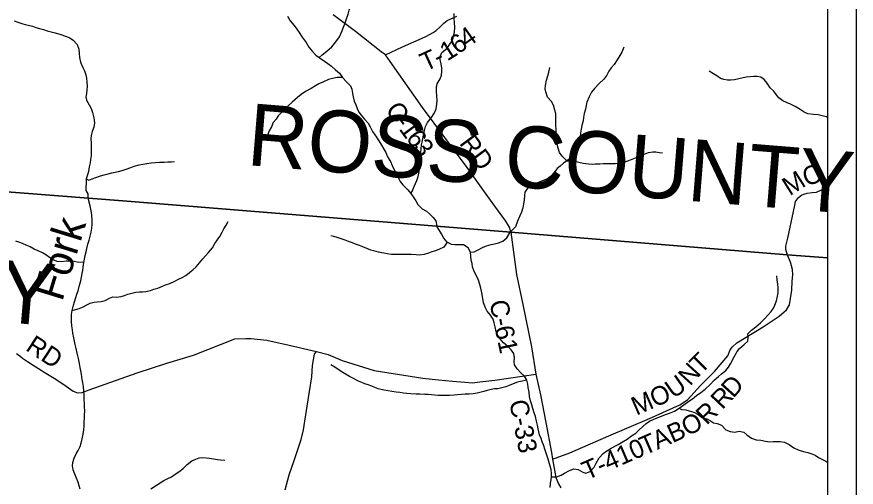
# Model space of a CAD drawing. Extents: x 0 to 34, y 0 to 22.
# Drawn here: x 6.52 to 9.087, y 18.193 to 19.631 of the extents above; entities that cross this region are included whole.
import ezdxf

# ---------------------------------------------------------------- set-up
doc = ezdxf.new("R2010")
doc.units = 0
for name, color, linetype in [('Default', 7, 'Continuous'), ('GM_X_County_Road', 7, 'Continuous'), ('GM_X_County_Road_Text', 7, 'Continuous'), ('GM_X_County_Text', 7, 'Continuous'), ('GM_X_Minor_River', 7, 'Continuous'), ('GM_X_Minor_River_Text', 7, 'Continuous'), ('GM_X_Township_Road', 7, 'Continuous'), ('GM_X_Township_Road_Text', 7, 'Continuous'), ('SH_Cut_Line', 7, 'Continuous')]:
    doc.layers.add(name, color=color, linetype=linetype)

msp = doc.modelspace()

# ---------------------------------------------------------------- linework, layer by layer
at = {"layer": 'Default'}
for points in [[(9.087, 13.8822), (2.1062, 13.8822), (2.1062, 20.9054), (9.087, 20.9054)], [(9, 18.8941), (9, 20.8), (5.8621, 20.8), (5.6166, 20.2359), (5.6047, 20.2229), (5.5951, 20.2127), (5.5869, 20.1933), (5.5834, 20.1771), (5.5783, 20.1528), (5.5679, 20.1313), (5.5496, 20.1004), (5.1782, 19.2598), (5.1554, 19.2083), (5.3224, 19.1939), (5.8337, 19.1499), (6.226, 19.1161), (6.8442, 19.0679), (8.0305, 18.9725), (8.8762, 18.9027)]]:
    msp.add_lwpolyline(points, close=True, dxfattribs=at)
msp.add_lwpolyline([(9, 14), (9, 18.8941), (8.8762, 18.9027), (8.0305, 18.9725), (6.8442, 19.0679), (6.226, 19.1161), (5.8337, 19.1499), (5.3224, 19.1939), (5.1554, 19.2083), (4.831, 19.2363), (4.7661, 18.9124), (5.0018, 18.1008), (4.9996, 18.0806), (4.937, 17.4953), (4.9239, 17.3511), (4.9207, 17.3435), (4.6758, 16.8903), (4.7194, 16.7424)], dxfattribs=at)
at = {"layer": 'GM_X_County_Road'}
for points in [[(7.6476, 19.5144), (7.6345, 19.5234), (7.556, 19.5857), (7.4872, 19.6361)], [(8.0308, 18.972), (8.0272, 18.9852), (8.015, 19.0059), (7.982, 19.0514), (7.9558, 19.0887), (7.897, 19.1704), (7.7601, 19.3538), (7.6612, 19.494), (7.6476, 19.5144)], [(8.8765, 18.9021), (8.872, 18.919), (8.8718, 18.9294), (8.8775, 18.954), (8.8952, 19.0358), (8.8996, 19.0544), (8.9013, 19.0665), (8.911, 19.0785), (8.9194, 19.0852), (8.9271, 19.0889), (8.9373, 19.0914), (8.9522, 19.0931), (8.9655, 19.0949), (8.9937, 19.1074), (9, 19.1103)], [(8.0308, 18.972), (8.0484, 18.8429), (8.0675, 18.7517), (8.0937, 18.6222), (8.1074, 18.5387)], [(6.5184, 18.6019), (6.529, 18.5943), (6.5377, 18.5871), (6.5525, 18.5775), (6.5703, 18.5657), (6.5942, 18.5505), (6.6032, 18.544), (6.6343, 18.5265), (6.6638, 18.5063), (6.6926, 18.4861), (6.7051, 18.4818), (6.7199, 18.4826), (6.7412, 18.4905), (6.8882, 18.5424), (6.9782, 18.5717), (7.0603, 18.5965), (7.1867, 18.6459), (7.2203, 18.6469), (7.2356, 18.6469), (7.2845, 18.6418), (7.3528, 18.6265), (7.4363, 18.6072), (7.472, 18.598), (7.5148, 18.5797), (7.6126, 18.5491), (7.7617, 18.5257), (7.8099, 18.5206), (7.852, 18.5167), (7.8903, 18.5135), (7.9138, 18.512), (7.9355, 18.5149), (7.9822, 18.5205), (8.1074, 18.5387)], [(8.1074, 18.5387), (8.1217, 18.4749), (8.1373, 18.391), (8.1556, 18.2991), (8.1578, 18.2782), (8.1638, 18.2448), (8.1687, 18.2228), (8.177, 18.2034), (8.1838, 18.1912)]]:
    msp.add_lwpolyline(points, dxfattribs=at)
at = {"layer": 'GM_X_Minor_River'}
for points in [[(7.4445, 19.5064), (7.4541, 19.5146), (7.4675, 19.5251), (7.4836, 19.5393), (7.4955, 19.5544), (7.5063, 19.569), (7.514, 19.5856), (7.5187, 19.5985), (7.5226, 19.6094), (7.5269, 19.6215), (7.5332, 19.6389), (7.5367, 19.6506), (7.541, 19.6619), (7.545, 19.6744), (7.5485, 19.6854), (7.5532, 19.6956), (7.5586, 19.7088), (7.5667, 19.7235), (7.5779, 19.7397), (7.5875, 19.7528), (7.5964, 19.7664), (7.6038, 19.7788), (7.6099, 19.7894), (7.6161, 19.8015)], [(7.7252, 19.0909), (7.7299, 19.0992), (7.7341, 19.1098), (7.7388, 19.1207), (7.7435, 19.1305), (7.747, 19.1426), (7.7502, 19.157), (7.7527, 19.1729), (7.7536, 19.1865), (7.7545, 19.2032), (7.7554, 19.215), (7.7563, 19.2278), (7.7572, 19.2384), (7.7604, 19.2528), (7.7632, 19.2687), (7.7664, 19.2835), (7.7699, 19.2952), (7.7761, 19.3073), (7.7884, 19.3231), (7.7973, 19.3366), (7.8028, 19.3494), (7.8044, 19.3638), (7.8053, 19.3744), (7.8047, 19.3892), (7.8037, 19.4037), (7.8035, 19.4154), (7.8055, 19.4256), (7.8144, 19.4407), (7.8187, 19.4517), (7.8199, 19.4634), (7.8193, 19.4733), (7.8172, 19.4873), (7.815, 19.5002), (7.8159, 19.5116), (7.8198, 19.5214), (7.8336, 19.533), (7.8417, 19.5435), (7.8513, 19.5567), (7.8548, 19.5665), (7.8584, 19.5851), (7.8593, 19.5983), (7.8588, 19.6135), (7.8574, 19.6257), (7.8572, 19.6405)], [(6.5115, 19.6185), (6.5228, 19.6142), (6.5383, 19.6087), (6.5549, 19.6048), (6.5682, 19.6016), (6.578, 19.5977), (6.5894, 19.5945), (6.6011, 19.5914), (6.6124, 19.5879), (6.6249, 19.5843), (6.637, 19.5815), (6.6548, 19.5764), (6.6684, 19.571), (6.6824, 19.5659), (6.6925, 19.5593), (6.7041, 19.5463), (6.7093, 19.5315), (6.7107, 19.5186), (6.7113, 19.5064), (6.7145, 19.4924), (6.7216, 19.476), (6.7268, 19.465), (6.7308, 19.4528), (6.733, 19.4429), (6.7344, 19.4308), (6.7346, 19.4175), (6.7341, 19.4069), (6.7325, 19.3959), (6.7308, 19.3861), (6.733, 19.3758), (6.7416, 19.3613), (6.7475, 19.3499), (6.7515, 19.3377), (6.7555, 19.3217), (6.7573, 19.3069), (6.7552, 19.2929), (6.7505, 19.2797), (6.747, 19.2683), (6.7461, 19.2574), (6.7471, 19.2448), (6.7477, 19.2319), (6.7472, 19.2217), (6.7471, 19.2065), (6.7454, 19.1948), (6.7438, 19.1846), (6.7414, 19.1717), (6.7386, 19.1581), (6.7362, 19.1479), (6.7323, 19.1358), (6.7321, 19.1206), (6.7305, 19.1097), (6.7311, 19.0994), (6.7371, 19.0895), (6.7373, 19.0816), (6.7382, 19.0758)], [(7.3473, 19.6321), (7.3554, 19.618), (7.3678, 19.6035), (7.3764, 19.5924), (7.3831, 19.5828), (7.3921, 19.5683), (7.4044, 19.5519), (7.4134, 19.5382), (7.4227, 19.5255), (7.4343, 19.5137), (7.4445, 19.5064), (7.4611, 19.4948), (7.4712, 19.4875), (7.4821, 19.4794), (7.4949, 19.4687), (7.507, 19.4587), (7.5155, 19.4453), (7.5283, 19.4323), (7.5399, 19.4201), (7.5443, 19.4094), (7.5469, 19.3976), (7.549, 19.3855), (7.5512, 19.3729), (7.5567, 19.3615), (7.5608, 19.3508), (7.566, 19.3394), (7.5727, 19.3299), (7.5836, 19.318), (7.594, 19.3057), (7.6007, 19.2947), (7.6078, 19.2798), (7.6197, 19.2623), (7.6268, 19.2516), (7.6354, 19.2386), (7.6421, 19.2256), (7.6484, 19.2157), (7.654, 19.2027), (7.6625, 19.1879), (7.6681, 19.1761), (7.6729, 19.1654), (7.6815, 19.1501), (7.6874, 19.1372), (7.6926, 19.1277), (7.7005, 19.1166), (7.7155, 19.1016), (7.7252, 19.0909), (7.7323, 19.0802), (7.7398, 19.0684), (7.7468, 19.0569), (7.7596, 19.0439), (7.7724, 19.0362), (7.7822, 19.0281), (7.7931, 19.017), (7.8009, 19.0071), (7.8045, 18.9904)], [(8.3761, 19.5376), (8.3699, 19.5229), (8.3644, 19.5119), (8.3556, 19.4988), (8.3463, 19.4845), (8.3375, 19.4743), (8.3305, 19.4645), (8.3243, 19.4525), (8.3155, 19.4404), (8.3005, 19.4269), (8.2871, 19.4115), (8.2775, 19.4006), (8.2701, 19.3855), (8.2635, 19.3697), (8.2611, 19.3598), (8.2587, 19.3481), (8.2555, 19.3352), (8.2531, 19.3228), (8.2515, 19.3122), (8.2483, 19.2982), (8.2463, 19.2876), (8.2435, 19.2747), (8.2426, 19.2645), (8.241, 19.2531), (8.2382, 19.2429), (8.2346, 19.2293), (8.2307, 19.2157), (8.2154, 19.2007), (8.2024, 19.1906), (8.192, 19.1831), (8.1817, 19.1745), (8.1721, 19.167), (8.1648, 19.1572), (8.1521, 19.1429), (8.1426, 19.1355), (8.1296, 19.1299), (8.1174, 19.1255), (8.1056, 19.1203), (8.0927, 19.114), (8.0831, 19.1076), (8.0735, 19.0949), (8.073, 19.0846), (8.0713, 19.0699), (8.0697, 19.0585), (8.0676, 19.0468), (8.0629, 19.0335), (8.0583, 19.0226), (8.0513, 19.0056), (8.0446, 18.989), (8.0287, 18.9724)], [(8.2024, 19.1906), (8.1881, 19.2048), (8.1799, 19.2162), (8.1751, 19.2292), (8.1729, 19.2402), (8.1715, 19.2504), (8.1697, 19.2611), (8.1691, 19.274), (8.1689, 19.2857), (8.1683, 19.2986), (8.1686, 19.3259), (8.1679, 19.3354), (8.1657, 19.3453), (8.1613, 19.3605), (8.155, 19.3719), (8.143, 19.3853), (8.1375, 19.4009), (8.1361, 19.4104), (8.1366, 19.4207), (8.1398, 19.4369), (8.1441, 19.4505), (8.1473, 19.4615), (8.1505, 19.4759)], [(8.6932, 19.4372), (8.6823, 19.4389), (8.6724, 19.4424), (8.6608, 19.4497), (8.651, 19.4563), (8.6378, 19.464)], [(7.5155, 19.4453), (7.4996, 19.4455), (7.4851, 19.4419), (7.4734, 19.4386), (7.4554, 19.4312), (7.4432, 19.426), (7.4337, 19.42), (7.4199, 19.4111), (7.4024, 19.4022), (7.389, 19.3928), (7.3783, 19.3842), (7.3615, 19.37), (7.3488, 19.3572), (7.3384, 19.3463), (7.3289, 19.3377), (7.3189, 19.3276), (7.3131, 19.3174), (7.3043, 19.3076), (7.2984, 19.2944), (7.2919, 19.2824), (7.2864, 19.2692), (7.2779, 19.2552)], [(9, 19.3219), (8.9962, 19.3245), (8.9826, 19.3284), (8.9705, 19.3312), (8.9565, 19.3325), (8.9394, 19.3338), (8.9281, 19.3396), (8.9153, 19.347), (8.9006, 19.3566), (8.8863, 19.3632), (8.8734, 19.369), (8.8625, 19.3733), (8.8504, 19.3829), (8.8426, 19.3936), (8.8347, 19.4032), (8.8235, 19.4139), (8.8145, 19.428), (8.8055, 19.4387), (8.795, 19.4457), (8.7844, 19.4477), (8.7738, 19.4482), (8.7628, 19.4475), (8.7506, 19.4465), (8.7278, 19.4411), (8.7149, 19.4382), (8.7035, 19.4371), (8.6932, 19.4372)], [(8.2024, 19.1906), (8.216, 19.1904), (8.2262, 19.1892), (8.2391, 19.1864), (8.2523, 19.1832), (8.2679, 19.1812), (8.2792, 19.1807), (8.2891, 19.181), (8.3032, 19.1816), (8.3138, 19.1818), (8.3248, 19.1825), (8.3373, 19.182), (8.3494, 19.1822), (8.3597, 19.1833), (8.3703, 19.185), (8.3806, 19.1872), (8.397, 19.1935), (8.4168, 19.2016), (8.4305, 19.2072), (8.4412, 19.2116), (8.4522, 19.2157), (8.4648, 19.2178), (8.4742, 19.2177), (8.4841, 19.2161), (8.4943, 19.2152)], [(6.7323, 19.1358), (6.7406, 19.1312), (6.7505, 19.1356), (6.7615, 19.1397), (6.7756, 19.1444), (6.7866, 19.1477), (6.7996, 19.151), (6.8106, 19.1536), (6.8205, 19.1557), (6.8304, 19.1575), (6.8418, 19.1612), (6.8547, 19.1649), (6.8681, 19.17), (6.8784, 19.1741), (6.8936, 19.1777), (6.905, 19.1803), (6.9179, 19.182), (6.9312, 19.1838), (6.9437, 19.1852), (6.9559, 19.1858), (6.971, 19.1864), (6.982, 19.187), (6.9927, 19.1877), (7.0022, 19.1887)], [(6.7264, 18.4495), (6.726, 18.4598), (6.7254, 18.4746), (6.725, 18.4875), (6.7241, 18.5004), (6.7221, 18.5125), (6.7201, 18.522), (6.7177, 18.5379), (6.7157, 18.5489), (6.7141, 18.5584), (6.7113, 18.5709), (6.7081, 18.586), (6.7042, 18.6023), (6.701, 18.6167), (6.6987, 18.6288), (6.6963, 18.639), (6.6939, 18.6496), (6.6915, 18.664), (6.6899, 18.6739), (6.6883, 18.6864), (6.687, 18.6997), (6.6869, 18.7103), (6.6872, 18.7209), (6.6894, 18.7331), (6.6934, 18.7491), (6.6964, 18.7593), (6.7004, 18.7723), (6.7038, 18.7826), (6.7071, 18.7932), (6.7119, 18.8103), (6.7152, 18.824), (6.7177, 18.8351), (6.7195, 18.8457), (6.7217, 18.8552), (6.7228, 18.8658), (6.7253, 18.8795), (6.7271, 18.8894), (6.7289, 18.9012), (6.7319, 18.9122), (6.734, 18.9221), (6.7373, 18.9358), (6.741, 18.9476), (6.7443, 18.9602), (6.7469, 18.9723), (6.7494, 18.9849), (6.7505, 18.9967), (6.75, 19.0096), (6.7491, 19.0228), (6.7483, 19.0327), (6.7463, 19.0425), (6.7439, 19.0524), (6.7382, 19.0758)], [(6.6894, 18.7331), (6.7106, 18.739), (6.7208, 18.7432), (6.7344, 18.7502), (6.7443, 18.7549), (6.756, 18.758), (6.7655, 18.7596), (6.778, 18.7609), (6.7897, 18.7636), (6.803, 18.7706), (6.8132, 18.7745), (6.8246, 18.7742), (6.8386, 18.7759), (6.8492, 18.7786), (6.8598, 18.7825), (6.8716, 18.7861), (6.8837, 18.7885), (6.8947, 18.7897), (6.9042, 18.7902), (6.9148, 18.7914), (6.9285, 18.7938), (6.9391, 18.7977), (6.9508, 18.8016), (6.9652, 18.8075), (6.975, 18.8113), (6.9879, 18.8157), (7.0034, 18.823), (7.0144, 18.8288), (7.0253, 18.8342), (7.0371, 18.8404), (7.0484, 18.8492), (7.0582, 18.8569), (7.068, 18.8665), (7.0789, 18.8788), (7.0883, 18.8906), (7.0973, 18.9002), (7.1063, 18.9101), (7.118, 18.9243), (7.1258, 18.9377), (7.1322, 18.948), (7.1404, 18.9594), (7.1475, 18.972), (7.1532, 18.9823), (7.1599, 18.9934), (7.1666, 19.0048)], [(7.9362, 18.8126), (7.9323, 18.8259), (7.9265, 18.8368), (7.9184, 18.8519), (7.9137, 18.8667), (7.9121, 18.8765), (7.9097, 18.8871), (7.9085, 18.8985), (7.9076, 18.911), (7.9003, 18.9246), (7.8858, 18.9332), (7.8732, 18.9335), (7.8599, 18.9333), (7.8497, 18.9344), (7.8363, 18.9415), (7.826, 18.9539), (7.8183, 18.9671), (7.8045, 18.9904)], [(7.9076, 18.911), (7.9182, 18.9119), (7.9307, 18.9185), (7.9443, 18.9254), (7.9568, 18.9301), (7.9708, 18.9348), (7.9807, 18.9368), (7.9932, 18.9396), (8.0064, 18.945), (8.0185, 18.955), (8.0287, 18.9724)], [(7.8363, 18.9415), (7.8254, 18.9269), (7.8126, 18.9207), (7.8005, 18.9153), (7.7895, 18.9118), (7.7789, 18.9083), (7.7653, 18.904), (7.752, 18.9023), (7.7417, 18.9026), (7.7261, 18.904), (7.7159, 18.9043), (7.7022, 18.9045), (7.6885, 18.904), (7.6783, 18.9039), (7.6658, 18.9042), (7.6528, 18.9059), (7.6262, 18.9117), (7.6121, 18.915), (7.6022, 18.9176), (7.59, 18.9224), (7.5786, 18.9272), (7.5683, 18.9317), (7.5561, 18.9361), (7.5462, 18.9394), (7.5344, 18.9443), (7.5241, 18.9479), (7.5119, 18.952), (7.4997, 18.9557), (7.4894, 18.959), (7.4799, 18.9616)], [(6.7253, 18.8795), (6.7044, 18.8809), (6.6949, 18.8823), (6.6846, 18.8833), (6.671, 18.8836), (6.6558, 18.8815), (6.6433, 18.8825), (6.6311, 18.8881), (6.62, 18.8945), (6.6081, 18.9035), (6.5986, 18.9091), (6.5849, 18.9158), (6.5734, 18.9206), (6.5605, 18.9273), (6.5509, 18.9317), (6.5372, 18.9377), (6.5265, 18.9421), (6.5166, 18.9451)], [(8.1555, 18.2249), (8.1715, 18.2247), (8.1851, 18.2301), (8.1953, 18.2356), (8.2097, 18.244), (8.2229, 18.2495), (8.237, 18.247), (8.2511, 18.2388), (8.2606, 18.2362), (8.2731, 18.2405), (8.2852, 18.2539), (8.2919, 18.2665), (8.3012, 18.2829), (8.3133, 18.2959), (8.3242, 18.304), (8.3371, 18.3125), (8.359, 18.3237), (8.3741, 18.3322), (8.3866, 18.3399), (8.3998, 18.3495), (8.4126, 18.3584), (8.4224, 18.3668), (8.4345, 18.3787), (8.445, 18.3871), (8.4548, 18.3944), (8.4658, 18.3995), (8.4787, 18.4053), (8.4915, 18.4104), (8.5036, 18.415), (8.5158, 18.4189), (8.5313, 18.4255), (8.5456, 18.4344), (8.5603, 18.4444), (8.5754, 18.4556), (8.586, 18.4629), (8.5985, 18.4733), (8.6117, 18.4825), (8.6249, 18.4925), (8.6403, 18.5071), (8.6527, 18.5197), (8.6655, 18.5312), (8.6754, 18.5389), (8.6882, 18.5493), (8.6961, 18.56), (8.7028, 18.5703), (8.714, 18.5917), (8.7234, 18.6073), (8.7305, 18.6169), (8.7444, 18.6292), (8.7554, 18.6391), (8.7568, 18.6513), (8.7555, 18.6615), (8.7665, 18.6726), (8.78, 18.683), (8.7947, 18.6953), (8.8068, 18.7079), (8.8177, 18.7202), (8.8267, 18.7302), (8.8339, 18.7397), (8.8379, 18.7496), (8.8428, 18.7626), (8.8461, 18.7766), (8.8479, 18.7873), (8.8485, 18.8036), (8.8476, 18.8131), (8.8456, 18.8264), (8.844, 18.8392)], [(8.1509, 18.1919), (8.1523, 18.2052), (8.1545, 18.2154), (8.1555, 18.2249), (8.1555, 18.2348), (8.1538, 18.2473), (8.1511, 18.2571), (8.1448, 18.2783), (8.1409, 18.2912), (8.1358, 18.306), (8.1304, 18.3219), (8.1269, 18.3317), (8.123, 18.3415), (8.1187, 18.3532), (8.1148, 18.371), (8.1124, 18.3824), (8.1096, 18.3949), (8.1057, 18.4089), (8.1018, 18.4203), (8.0979, 18.4331), (8.0947, 18.4449), (8.0912, 18.457), (8.0881, 18.4706), (8.0864, 18.4831), (8.084, 18.4979), (8.0828, 18.5074), (8.0793, 18.5199), (8.0727, 18.5323), (8.0609, 18.5425), (8.0497, 18.5545), (8.042, 18.5666), (8.0412, 18.5768), (8.0418, 18.5886), (8.0395, 18.6011), (8.0321, 18.6124), (8.0218, 18.6226), (8.0084, 18.6342), (7.9969, 18.647), (7.99, 18.6591), (7.9857, 18.6689), (7.9825, 18.6829), (7.9798, 18.6954), (7.9766, 18.7064), (7.9682, 18.7192), (7.9586, 18.7313), (7.9528, 18.7414), (7.9473, 18.7562), (7.9433, 18.782), (7.9413, 18.7918), (7.9393, 18.8013), (7.9362, 18.8126)], [(8.0793, 18.5199), (8.0607, 18.5163), (8.0508, 18.5143), (8.038, 18.5088), (8.0255, 18.5034), (8.0153, 18.4995), (8.0035, 18.4964), (7.991, 18.494), (7.9812, 18.4931), (7.9709, 18.4911), (7.9588, 18.4883), (7.9482, 18.4856), (7.9277, 18.4801), (7.9156, 18.4784), (7.9031, 18.4776), (7.8913, 18.4771), (7.8799, 18.4762), (7.8681, 18.4749), (7.8571, 18.4741), (7.8427, 18.4728), (7.8321, 18.4727), (7.8211, 18.473), (7.8089, 18.4732), (7.7983, 18.4743), (7.7884, 18.4753), (7.7774, 18.476), (7.7675, 18.4766), (7.7523, 18.4769), (7.7409, 18.4775), (7.7253, 18.4781), (7.7128, 18.4791), (7.7025, 18.4802), (7.6911, 18.482), (7.6801, 18.4834), (7.6664, 18.4855), (7.6554, 18.4873), (7.6421, 18.4899), (7.6249, 18.4939), (7.615, 18.4976), (7.6055, 18.5013), (7.5948, 18.5053), (7.5845, 18.509), (7.575, 18.5127), (7.5651, 18.5172), (7.5498, 18.525), (7.5376, 18.5317), (7.5273, 18.537), (7.5166, 18.5437), (7.5056, 18.5508), (7.4926, 18.5598), (7.4807, 18.5665)], [(6.7132, 18.1871), (6.7108, 18.197), (6.7073, 18.2083), (6.7022, 18.2201), (6.6968, 18.2325), (6.6921, 18.2461), (6.6905, 18.2583), (6.6908, 18.2685), (6.6956, 18.2815), (6.7016, 18.2948), (6.7072, 18.3055), (6.7132, 18.3177), (6.7165, 18.328), (6.7202, 18.3409), (6.7231, 18.355), (6.7252, 18.3679), (6.7259, 18.3808), (6.7262, 18.3934), (6.7268, 18.404), (6.7271, 18.4135), (6.7274, 18.4275), (6.7269, 18.4374), (6.7264, 18.4495)], [(8.5456, 18.4344), (8.5529, 18.4303), (8.5662, 18.4293), (8.5765, 18.4267), (8.5902, 18.4223), (8.6035, 18.4152), (8.6165, 18.4051), (8.6306, 18.4018), (8.6413, 18.3962), (8.6508, 18.3895), (8.6615, 18.3873), (8.6752, 18.3829), (8.6882, 18.3682), (8.7016, 18.3634), (8.7156, 18.3613), (8.7289, 18.3641), (8.743, 18.3608), (8.7526, 18.3529), (8.7667, 18.3428), (8.7815, 18.338), (8.7952, 18.3366), (8.8093, 18.3337), (8.8222, 18.3316), (8.8329, 18.3321), (8.8454, 18.3329), (8.8549, 18.3326), (8.8678, 18.3301), (8.8816, 18.3238), (8.8961, 18.3133), (8.909, 18.307), (8.9186, 18.304), (8.9296, 18.3011), (8.9395, 18.2985), (8.9513, 18.2952), (8.9616, 18.2908), (8.9715, 18.2841), (8.9818, 18.2788), (8.9937, 18.2721), (9, 18.2687)], [(6.9296, 18.1877), (6.9443, 18.1973), (6.9579, 18.2066), (6.9696, 18.2139), (6.9814, 18.2197), (6.9927, 18.2251), (7.0037, 18.2328), (7.0157, 18.2398), (7.0289, 18.2505), (7.0406, 18.262), (7.0553, 18.2732), (7.067, 18.279), (7.078, 18.2825), (7.0879, 18.2834), (7.0985, 18.2827), (7.1096, 18.2817), (7.1217, 18.2799), (7.1335, 18.2777), (7.143, 18.2767), (7.1559, 18.2753)]]:
    msp.add_lwpolyline(points, dxfattribs=at)
at = {"layer": 'GM_X_Township_Road'}
for points in [[(7.6476, 19.5144), (7.6993, 19.5386), (7.7683, 19.5698), (7.7837, 19.5774), (7.7933, 19.5829), (7.8025, 19.5884), (7.8161, 19.6014), (7.8257, 19.6107), (7.8362, 19.6192), (7.8653, 19.6327)], [(8.1578, 18.2782), (8.2107, 18.2982), (8.3304, 18.3494), (8.4546, 18.4033), (8.5473, 18.4448), (8.5713, 18.4595), (8.6105, 18.5034), (8.6539, 18.5462), (8.6939, 18.5939), (8.7019, 18.6124), (8.7084, 18.6219), (8.7217, 18.634), (8.8023, 18.6831), (8.851, 18.7152), (8.8738, 18.7349), (8.8826, 18.7504), (8.89, 18.7956), (8.8912, 18.8229), (8.8935, 18.8424), (8.8922, 18.8585), (8.8857, 18.8806), (8.8765, 18.9021)], [(7.3405, 18.1844), (7.3528, 18.2312), (7.3681, 18.275), (7.3895, 18.3382), (7.3966, 18.3678), (7.4078, 18.4401), (7.4221, 18.5298), (7.4241, 18.5644), (7.4302, 18.599), (7.4363, 18.6072)]]:
    msp.add_lwpolyline(points, dxfattribs=at)
at = {"layer": 'SH_Cut_Line'}
for points in [[(9, 18.8941), (9, 20.8), (2.2, 20.8), (2.2, 19.4329), (2.7961, 19.3885), (3.1893, 19.3592), (4.7641, 19.2419), (4.831, 19.2363), (5.1554, 19.2083), (5.3224, 19.1939), (5.8337, 19.1499), (6.226, 19.1161), (6.8442, 19.0679), (8.0305, 18.9725), (8.8762, 18.9027)], [(2.2, 19.4329), (2.2, 14), (9, 14), (9, 18.8941), (8.8762, 18.9027), (8.0305, 18.9725), (6.8442, 19.0679), (6.226, 19.1161), (5.8337, 19.1499), (5.3224, 19.1939), (5.1554, 19.2083), (4.831, 19.2363), (4.7641, 19.2419), (3.1893, 19.3592), (2.7961, 19.3885)]]:
    msp.add_lwpolyline(points, close=True, dxfattribs=at)

# ---------------------------------------------------------------- texts
at = {"layer": 'GM_X_County_Road_Text'}
for s, height, rotation, p in [('C', 0.0568, 304.8982, (7.6453, 19.3461)), ('-', 0.0568, 306.0577, (7.6727, 19.3068)), ('1', 0.0568, 306.4892, (7.6868, 19.2876)), ('6', 0.0568, 306.9237, (7.7079, 19.259)), ('3', 0.0568, 307.0274, (7.7289, 19.231)), ('RD', 0.05682, 306.5722, (7.8712, 19.2437)), ('O', 0.0568, 15.2476, (8.9319, 19.113)), ('M', 0.0568, 32.2158, (8.8838, 19.0819)), ('C-61', 0.05682, 281.7823, (7.9649, 18.7594)), ('RD', 0.05682, 326.5822, (6.5438, 18.6132)), ('C-33', 0.05682, 281.0414, (8.0255, 18.4548))]:
    msp.add_text(s, height=height, rotation=rotation, dxfattribs=at).set_placement(p)
at = {"layer": 'GM_X_County_Text'}
for s, rotation, p in [('ROSS COUNTY', 355.3773, (7.2204, 19.1777)), ('PIKE COUNTY', 355.1489, (4.9178, 18.83))]:
    msp.add_text(s, height=0.189394, rotation=rotation, dxfattribs=at).set_placement(p)
at = {"layer": 'GM_X_Minor_River_Text'}
msp.add_text('Fork', height=0.09467, rotation=72.909, dxfattribs=at).set_placement((6.6582, 18.7574))
at = {"layer": 'GM_X_Township_Road_Text'}
for s, height, rotation, p in [('4', 0.0568, 35.1532, (7.8973, 19.5343)), ('6', 0.0568, 34.9634, (7.8685, 19.5141)), ('1', 0.0568, 32.1313, (7.8363, 19.4938)), ('T', 0.0568, 24.581, (7.7694, 19.4622)), ('-', 0.0568, 25.504, (7.8089, 19.4803)), ('T', 0.0568, 45.1606, (8.6121, 18.5365)), ('N', 0.0568, 47.8531, (8.5791, 18.4999)), ('U', 0.0568, 35.2155, (8.528, 18.462)), ('D', 0.0568, 48.0662, (8.7109, 18.4629)), ('M', 0.0568, 23.5639, (8.4147, 18.4111)), ('O', 0.0568, 23.6879, (8.4713, 18.4358)), ('R', 0.0568, 46.5098, (8.6776, 18.4278)), ('R', 0.0568, 43.562, (8.6295, 18.3807)), ('O', 0.0568, 27.1557, (8.5706, 18.3476)), ('B', 0.0568, 24.137, (8.525, 18.3271)), ('T', 0.0568, 23.6392, (8.4398, 18.2898)), ('A', 0.0568, 23.7164, (8.4789, 18.3068)), ('T-410', 0.05682, 23.3083, (8.2635, 18.2138))]:
    msp.add_text(s, height=height, rotation=rotation, dxfattribs=at).set_placement(p)

doc.saveas('drawing.dxf')
